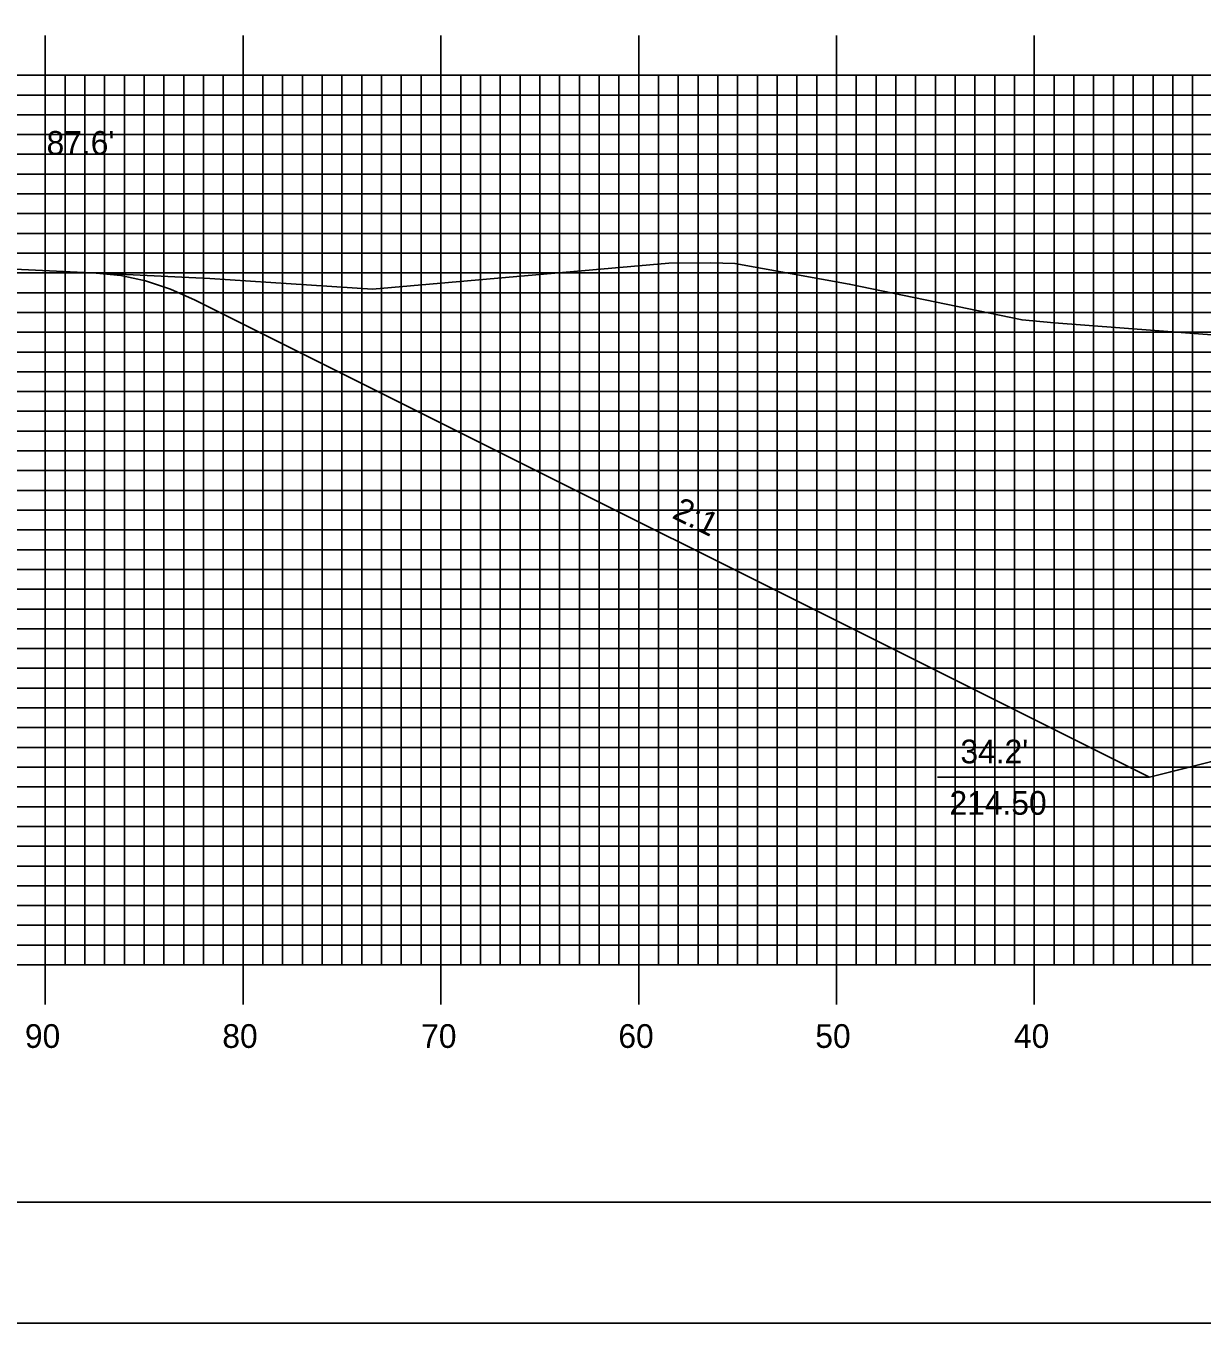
# Model space of a CAD drawing. Extents: x 1816489 to 1816833, y 442591 to 442811.
# Drawn here: x 1816564.1 to 1816623.6, y 442590.5 to 442656.2 of the extents above; entities that cross this region are included whole.
import ezdxf

# ---------------------------------------------------------------- set-up
doc = ezdxf.new("R2010")
doc.units = 0
for name, color, linetype in [('ANNOTATION', 7, 'Continuous'), ('BORDER', 7, 'Continuous'), ('D_Roadway_Centerline', 7, 'Continuous'), ('D_Roadway_SlopeLines', 7, 'Continuous'), ('D_Text_Standard', 7, 'Continuous'), ('H_V ANNOTATION', 7, 'Continuous'), ('MAJOR', 7, 'Continuous'), ('MINOR', 7, 'Continuous'), ('PDRAIN', 7, 'Continuous'), ('PLOT BOUNDARY', 7, 'Continuous'), ('S_Roadway_Centerline', 7, 'Continuous')]:
    doc.layers.add(name, color=color, linetype=linetype)

msp = doc.modelspace()

# ---------------------------------------------------------------- linework, layer by layer
at = {"layer": 'BORDER'}
msp.add_lwpolyline([(1816505.473, 442596.665), (1816825.473, 442596.665), (1816825.473, 442806.665), (1816505.473, 442806.665)], close=True, dxfattribs=at)
at = {"layer": 'D_Roadway_Centerline'}
msp.add_lwpolyline([(1816567.648, 442643.659), (1816568.898, 442643.529), (1816570.148, 442643.258), (1816571.398, 442642.845), (1816572.648, 442642.291), (1816620.899, 442618.166), (1816624.899, 442619.166), (1816635.073, 442621.709), (1816643.073, 442622.029), (1816655.073, 442622.269), (1816667.073, 442622.029), (1816675.073, 442621.709), (1816685.247, 442619.166), (1816689.247, 442618.166), (1816717.052, 442632.068), (1816718.302, 442632.599), (1816719.552, 442632.941), (1816720.802, 442633.095), (1816722.052, 442633.061)], dxfattribs=at)
at = {"layer": 'D_Roadway_SlopeLines'}
for points in [[(1816620.899, 442618.166), (1816572.648, 442642.291), (1816571.398, 442642.845), (1816570.148, 442643.258), (1816568.898, 442643.529), (1816567.648, 442643.659)], [(1816635.073, 442621.709), (1816620.899, 442618.166)]]:
    msp.add_lwpolyline(points, dxfattribs=at)
at = {"layer": 'MAJOR'}
for p, q in [((1816565.073, 442655.669), (1816565.073, 442653.665)), ((1816575.073, 442655.669), (1816575.073, 442653.665)), ((1816585.073, 442655.669), (1816585.073, 442653.665)), ((1816595.073, 442655.669), (1816595.073, 442653.665)), ((1816605.073, 442655.669), (1816605.073, 442653.665)), ((1816615.073, 442655.669), (1816615.073, 442653.665)), ((1816515.073, 442653.665), (1816795.073, 442653.665)), ((1816515.073, 442653.665), (1816795.073, 442653.665)), ((1816565.073, 442608.665), (1816565.073, 442653.665)), ((1816575.073, 442608.665), (1816575.073, 442653.665)), ((1816585.073, 442608.665), (1816585.073, 442653.665)), ((1816595.073, 442608.665), (1816595.073, 442653.665)), ((1816605.073, 442608.665), (1816605.073, 442653.665)), ((1816615.073, 442608.665), (1816615.073, 442653.665)), ((1816515.073, 442648.665), (1816795.073, 442648.665)), ((1816515.073, 442643.665), (1816795.073, 442643.665)), ((1816515.073, 442638.665), (1816795.073, 442638.665)), ((1816515.073, 442633.665), (1816795.073, 442633.665)), ((1816515.073, 442628.665), (1816795.073, 442628.665)), ((1816515.073, 442623.665), (1816795.073, 442623.665)), ((1816515.073, 442618.665), (1816795.073, 442618.665)), ((1816515.073, 442613.665), (1816795.073, 442613.665)), ((1816515.073, 442608.665), (1816795.073, 442608.665)), ((1816515.073, 442608.665), (1816795.073, 442608.665)), ((1816565.073, 442606.661), (1816565.073, 442608.665)), ((1816575.073, 442606.661), (1816575.073, 442608.665)), ((1816585.073, 442606.661), (1816585.073, 442608.665)), ((1816595.073, 442606.661), (1816595.073, 442608.665)), ((1816605.073, 442606.661), (1816605.073, 442608.665)), ((1816615.073, 442606.661), (1816615.073, 442608.665))]:
    msp.add_line(p, q, dxfattribs=at)
at = {"layer": 'MINOR'}
for p, q in [((1816566.073, 442608.665), (1816566.073, 442653.665)), ((1816567.073, 442608.665), (1816567.073, 442653.665)), ((1816568.073, 442608.665), (1816568.073, 442653.665)), ((1816569.073, 442608.665), (1816569.073, 442653.665)), ((1816570.073, 442608.665), (1816570.073, 442653.665)), ((1816571.073, 442608.665), (1816571.073, 442653.665)), ((1816572.073, 442608.665), (1816572.073, 442653.665)), ((1816573.073, 442608.665), (1816573.073, 442653.665)), ((1816574.073, 442608.665), (1816574.073, 442653.665)), ((1816576.073, 442608.665), (1816576.073, 442653.665)), ((1816577.073, 442608.665), (1816577.073, 442653.665)), ((1816578.073, 442608.665), (1816578.073, 442653.665)), ((1816579.073, 442608.665), (1816579.073, 442653.665)), ((1816580.073, 442608.665), (1816580.073, 442653.665)), ((1816581.073, 442608.665), (1816581.073, 442653.665)), ((1816582.073, 442608.665), (1816582.073, 442653.665)), ((1816583.073, 442608.665), (1816583.073, 442653.665)), ((1816584.073, 442608.665), (1816584.073, 442653.665)), ((1816586.073, 442608.665), (1816586.073, 442653.665)), ((1816587.073, 442608.665), (1816587.073, 442653.665)), ((1816588.073, 442608.665), (1816588.073, 442653.665)), ((1816589.073, 442608.665), (1816589.073, 442653.665)), ((1816590.073, 442608.665), (1816590.073, 442653.665)), ((1816591.073, 442608.665), (1816591.073, 442653.665)), ((1816592.073, 442608.665), (1816592.073, 442653.665)), ((1816593.073, 442608.665), (1816593.073, 442653.665)), ((1816594.073, 442608.665), (1816594.073, 442653.665)), ((1816596.073, 442608.665), (1816596.073, 442653.665)), ((1816597.073, 442608.665), (1816597.073, 442653.665)), ((1816598.073, 442608.665), (1816598.073, 442653.665)), ((1816599.073, 442608.665), (1816599.073, 442653.665)), ((1816600.073, 442608.665), (1816600.073, 442653.665)), ((1816601.073, 442608.665), (1816601.073, 442653.665)), ((1816602.073, 442608.665), (1816602.073, 442653.665)), ((1816603.073, 442608.665), (1816603.073, 442653.665)), ((1816604.073, 442608.665), (1816604.073, 442653.665)), ((1816606.073, 442608.665), (1816606.073, 442653.665)), ((1816607.073, 442608.665), (1816607.073, 442653.665)), ((1816608.073, 442608.665), (1816608.073, 442653.665)), ((1816609.073, 442608.665), (1816609.073, 442653.665)), ((1816610.073, 442608.665), (1816610.073, 442653.665)), ((1816611.073, 442608.665), (1816611.073, 442653.665)), ((1816612.073, 442608.665), (1816612.073, 442653.665)), ((1816613.073, 442608.665), (1816613.073, 442653.665)), ((1816614.073, 442608.665), (1816614.073, 442653.665)), ((1816616.073, 442608.665), (1816616.073, 442653.665)), ((1816617.073, 442608.665), (1816617.073, 442653.665)), ((1816618.073, 442608.665), (1816618.073, 442653.665)), ((1816619.073, 442608.665), (1816619.073, 442653.665)), ((1816620.073, 442608.665), (1816620.073, 442653.665)), ((1816621.073, 442608.665), (1816621.073, 442653.665)), ((1816622.073, 442608.665), (1816622.073, 442653.665)), ((1816623.073, 442608.665), (1816623.073, 442653.665)), ((1816515.073, 442652.665), (1816795.073, 442652.665)), ((1816515.073, 442651.665), (1816795.073, 442651.665)), ((1816515.073, 442650.665), (1816795.073, 442650.665)), ((1816515.073, 442649.665), (1816795.073, 442649.665)), ((1816515.073, 442647.665), (1816795.073, 442647.665)), ((1816515.073, 442646.665), (1816795.073, 442646.665)), ((1816515.073, 442645.665), (1816795.073, 442645.665)), ((1816515.073, 442644.665), (1816795.073, 442644.665)), ((1816515.073, 442642.665), (1816795.073, 442642.665)), ((1816515.073, 442641.665), (1816795.073, 442641.665)), ((1816515.073, 442640.665), (1816795.073, 442640.665)), ((1816515.073, 442639.665), (1816795.073, 442639.665)), ((1816515.073, 442637.665), (1816795.073, 442637.665)), ((1816515.073, 442636.665), (1816795.073, 442636.665)), ((1816515.073, 442635.665), (1816795.073, 442635.665)), ((1816515.073, 442634.665), (1816795.073, 442634.665)), ((1816515.073, 442632.665), (1816795.073, 442632.665)), ((1816515.073, 442631.665), (1816795.073, 442631.665)), ((1816515.073, 442630.665), (1816795.073, 442630.665)), ((1816515.073, 442629.665), (1816795.073, 442629.665)), ((1816515.073, 442627.665), (1816795.073, 442627.665)), ((1816515.073, 442626.665), (1816795.073, 442626.665)), ((1816515.073, 442625.665), (1816795.073, 442625.665)), ((1816515.073, 442624.665), (1816795.073, 442624.665)), ((1816515.073, 442622.665), (1816795.073, 442622.665)), ((1816515.073, 442621.665), (1816795.073, 442621.665)), ((1816515.073, 442620.665), (1816795.073, 442620.665)), ((1816515.073, 442619.665), (1816795.073, 442619.665)), ((1816515.073, 442617.665), (1816795.073, 442617.665)), ((1816515.073, 442616.665), (1816795.073, 442616.665)), ((1816515.073, 442615.665), (1816795.073, 442615.665)), ((1816515.073, 442614.665), (1816795.073, 442614.665)), ((1816515.073, 442612.665), (1816795.073, 442612.665)), ((1816515.073, 442611.665), (1816795.073, 442611.665)), ((1816515.073, 442610.665), (1816795.073, 442610.665)), ((1816515.073, 442609.665), (1816795.073, 442609.665))]:
    msp.add_line(p, q, dxfattribs=at)
at = {"layer": 'PDRAIN'}
msp.add_line((1816610.176, 442618.166), (1816620.899, 442618.166), dxfattribs=at)
at = {"layer": 'PLOT BOUNDARY'}
msp.add_lwpolyline([(1816489.286, 442590.547), (1816829.286, 442590.547), (1816829.286, 442810.547), (1816489.286, 442810.547)], close=True, dxfattribs=at)
at = {"layer": 'S_Roadway_Centerline'}
msp.add_lwpolyline([(1816549.048, 442644.54), (1816573.391, 442643.387), (1816581.615, 442642.85), (1816596.597, 442644.164), (1816598.715, 442644.176), (1816599.937, 442644.148), (1816605.718, 442643.1), (1816614.452, 442641.285), (1816616.076, 442641.146), (1816628.026, 442640.237), (1816632.984, 442640.114), (1816641.806, 442639.39), (1816650.657, 442638.868), (1816655.939, 442638.7), (1816667.72, 442637.466), (1816674.808, 442637.145), (1816684.828, 442636.605), (1816695.528, 442635.592)], dxfattribs=at)

# ---------------------------------------------------------------- texts
at = {"layer": 'ANNOTATION'}
msp.add_text('2:1', height=1.2, rotation=333.43495, dxfattribs=at).set_placement((1816596.708, 442631.297))
for s, p in [("34.2'", (1816611.337, 442618.858)), ('214.50', (1816610.786, 442616.258))]:
    msp.add_text(s, height=1.2, dxfattribs=at).set_placement(p)
at = {"layer": 'D_Text_Standard'}
msp.add_text("87.6'", height=1.2, dxfattribs=at).set_placement((1816565.14, 442649.643))
at = {"layer": 'H_V ANNOTATION'}
for s, p in [('90', (1816564.045, 442604.465)), ('80', (1816574.024, 442604.465)), ('70', (1816584.077, 442604.465)), ('60', (1816594.045, 442604.465)), ('50', (1816604.002, 442604.465)), ('40', (1816614.045, 442604.465))]:
    msp.add_text(s, height=1.2, dxfattribs=at).set_placement(p)

doc.saveas('drawing.dxf')
